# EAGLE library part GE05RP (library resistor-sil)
SIL RESISTOR
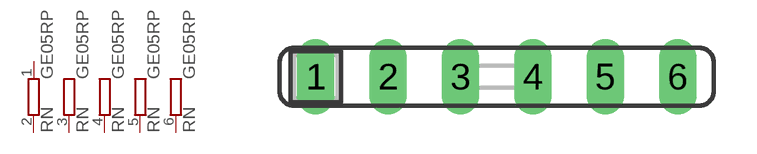
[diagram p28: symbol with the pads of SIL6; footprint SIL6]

Designator prefix RN; gates A=R-PV B=R-PV1 C=R-PV1 D=R-PV1 E=R-PV1

## GE05RP (OC_FARNELL: unknown; OC_NEWARK: unknown)  [SIL6]
1  A:1  pas
2  A:2  pas
3  B:2  pas
4  C:2  pas
5  D:2  pas
6  E:2  pas

## Footprint SIL6 (pad centres in mm)
Single In Line
drill 0.813 long: 1 -6.35,0; 2 -3.81,0; 3 -1.27,0; 4 1.27,0; 5 3.81,0; 6 6.35,0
